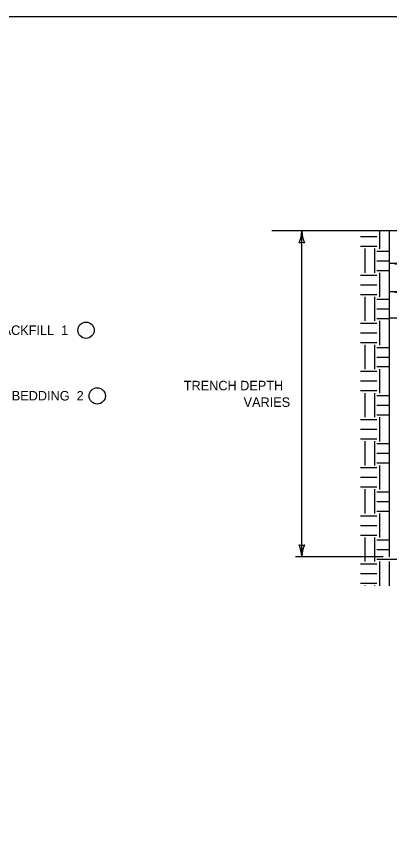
# Model space of a CAD drawing. Extents: x 49991.4 to 50061.4, y 49960.6 to 50011.4.
# Drawn here: x 50010.06 to 50012.41, y 49993.73 to 49999 of the extents above; entities that cross this region are included whole.
import ezdxf

# ---------------------------------------------------------------- set-up
doc = ezdxf.new("R2010")
doc.units = 0
for name, color, linetype in [('Level 1', 7, 'Continuous'), ('Level 2', 7, 'Continuous'), ('Level 3', 7, 'Continuous')]:
    doc.layers.add(name, color=color, linetype=linetype)

msp = doc.modelspace()

# ---------------------------------------------------------------- linework, layer by layer
at = {"layer": 'Level 1'}
for p, q in [((50015.4944, 49997.6424), (50011.6711, 49997.6424)), ((50012.3517, 49997.6424), (50012.3517, 49997.5292)), ((50012.4129, 49997.6424), (50012.4129, 49997.5292)), ((50012.4143, 49997.0926), (50012.4143, 49997.6424)), ((50012.231, 49997.6067), (50012.3353, 49997.6067)), ((50012.231, 49997.5455), (50012.3353, 49997.5455)), ((50012.2589, 49997.5303), (50012.2589, 49997.3774)), ((50012.32, 49997.5303), (50012.32, 49997.3774)), ((50012.3353, 49997.515), (50012.4143, 49997.515)), ((50012.3353, 49997.4538), (50012.4143, 49997.4538)), ((50012.231, 49997.3632), (50012.3353, 49997.3632)), ((50012.3353, 49997.3927), (50012.4143, 49997.3927)), ((50012.3517, 49997.3774), (50012.3517, 49997.2245)), ((50012.4129, 49997.3774), (50012.4129, 49997.2245)), ((50012.231, 49997.302), (50012.3353, 49997.302)), ((50012.231, 49997.2408), (50012.3353, 49997.2408)), ((50012.2589, 49997.2256), (50012.2589, 49997.0727)), ((50012.32, 49997.2256), (50012.32, 49997.0727)), ((50012.3353, 49997.2103), (50012.4143, 49997.2103)), ((50012.3353, 49997.1491), (50012.4143, 49997.1491)), ((50012.4143, 49995.58), (50012.4143, 49997.0926)), ((50012.4143, 49997.0926), (50014.7511, 49997.0926)), ((50012.4143, 49995.58), (50012.4143, 49997.0926)), ((50012.231, 49997.0585), (50012.3353, 49997.0585)), ((50012.3353, 49997.088), (50012.4143, 49997.088)), ((50012.3517, 49997.0727), (50012.3517, 49996.9198)), ((50012.4129, 49997.0727), (50012.4129, 49996.9198)), ((50012.231, 49996.9973), (50012.3353, 49996.9973)), ((50012.231, 49996.9362), (50012.3353, 49996.9362)), ((50012.2589, 49996.9209), (50012.2589, 49996.768)), ((50012.32, 49996.9209), (50012.32, 49996.768)), ((50012.3353, 49996.9056), (50012.4143, 49996.9056)), ((50012.3353, 49996.8444), (50012.4143, 49996.8444)), ((50012.3353, 49996.7833), (50012.4143, 49996.7833)), ((50012.231, 49996.7538), (50012.3353, 49996.7538)), ((50012.3517, 49996.768), (50012.3517, 49996.6151)), ((50012.4129, 49996.768), (50012.4129, 49996.6151)), ((50012.231, 49996.6926), (50012.3353, 49996.6926)), ((50012.231, 49996.6315), (50012.3353, 49996.6315)), ((50012.2589, 49996.6162), (50012.2589, 49996.4633)), ((50012.32, 49996.6162), (50012.32, 49996.4633)), ((50012.3353, 49996.6009), (50012.4143, 49996.6009)), ((50012.3353, 49996.5397), (50012.4143, 49996.5397)), ((50012.3353, 49996.4786), (50012.4143, 49996.4786)), ((50012.3517, 49996.4633), (50012.3517, 49996.3104)), ((50012.4129, 49996.4633), (50012.4129, 49996.3104)), ((50012.231, 49996.4491), (50012.3353, 49996.4491)), ((50012.231, 49996.3879), (50012.3353, 49996.3879)), ((50012.231, 49996.3268), (50012.3353, 49996.3268)), ((50012.2589, 49996.3115), (50012.2589, 49996.1586)), ((50012.32, 49996.3115), (50012.32, 49996.1586)), ((50012.3353, 49996.2962), (50012.4143, 49996.2962)), ((50012.3353, 49996.235), (50012.4143, 49996.235)), ((50012.231, 49996.1444), (50012.3353, 49996.1444)), ((50012.3353, 49996.1739), (50012.4143, 49996.1739)), ((50012.3517, 49996.1586), (50012.3517, 49996.0057)), ((50012.4129, 49996.1586), (50012.4129, 49996.0057)), ((50012.231, 49996.0832), (50012.3353, 49996.0832)), ((50012.231, 49996.0221), (50012.3353, 49996.0221)), ((50012.2589, 49996.0068), (50012.2589, 49995.8539)), ((50012.32, 49996.0068), (50012.32, 49995.8539)), ((50012.3353, 49995.9915), (50012.4143, 49995.9915)), ((50012.3353, 49995.9303), (50012.4143, 49995.9303)), ((50012.231, 49995.8397), (50012.3353, 49995.8397)), ((50012.3353, 49995.8692), (50012.4143, 49995.8692)), ((50012.3517, 49995.8539), (50012.3517, 49995.701)), ((50012.4129, 49995.8539), (50012.4129, 49995.701)), ((50012.231, 49995.7785), (50012.3353, 49995.7785)), ((50012.231, 49995.7174), (50012.3353, 49995.7174)), ((50012.2589, 49995.7021), (50012.2589, 49995.5492)), ((50012.32, 49995.7021), (50012.32, 49995.5492)), ((50012.3353, 49995.6868), (50012.4143, 49995.6868)), ((50012.3353, 49995.6256), (50012.4143, 49995.6256)), ((50012.3353, 49995.5645), (50012.4882, 49995.5645)), ((50012.231, 49995.535), (50012.3353, 49995.535)), ((50012.3517, 49995.5492), (50012.3517, 49995.3967)), ((50012.4129, 49995.5492), (50012.4129, 49995.3967)), ((50012.231, 49995.4738), (50012.3353, 49995.4738)), ((50012.231, 49995.4127), (50012.3353, 49995.4127)), ((50012.2589, 49995.3974), (50012.2589, 49995.3967)), ((50012.32, 49995.3974), (50012.32, 49995.3967))]:
    msp.add_line(p, q, dxfattribs=at)
msp.add_lwpolyline([(49999.3835, 49998.9992), (50016.7501, 49998.9992), (50016.7501, 49987.7988), (49999.3835, 49987.7988)], close=True, dxfattribs=at)
at = {"layer": 'Level 2'}
for centre in [(50010.4963, 49997.014), (50010.5667, 49996.5983)]:
    msp.add_circle(centre, 0.0517, dxfattribs=at)
at = {"layer": 'Level 3'}
for p, q in [((50011.8606, 49995.58), (50011.8606, 49997.6424)), ((50012.4143, 49997.4378), (50014.7511, 49997.4378)), ((50012.4143, 49997.2583), (50013.239, 49997.2583)), ((50012.3743, 49995.58), (50011.8206, 49995.58))]:
    msp.add_line(p, q, dxfattribs=at)
for centre, radius, start, end in [((50011.6385, 49997.6515), 0.2223, 337.456, 357.6395), ((50012.0933, 49997.6539), 0.233, 182.8273, 202.0772), ((50011.8606, 49997.5141), 0.0548, 72.1388, 107.8612), ((50012.4052, 49997.2156), 0.2223, 67.456, 87.6395), ((50012.4052, 49997.0362), 0.2223, 67.456, 87.6395), ((50011.8606, 49995.7083), 0.0548, 252.1388, 287.8612), ((50011.6279, 49995.5685), 0.233, 2.8273, 22.0772), ((50012.0827, 49995.5709), 0.2223, 157.456, 177.6395)]:
    msp.add_arc(centre, radius, start, end, dxfattribs=at)

# ---------------------------------------------------------------- texts
at = {"layer": 'Level 2'}
for s, p in [('TRENCH BACKFILL  1', (50009.5583, 49996.984)), ('TRENCH DEPTH', (50011.1144, 49996.6337)), ('GRANULAR BEDDING  2', (50009.5583, 49996.5692)), ('VARIES', (50011.4926, 49996.5287))]:
    msp.add_text(s, height=0.06, dxfattribs=at).set_placement(p)

doc.saveas('drawing.dxf')
